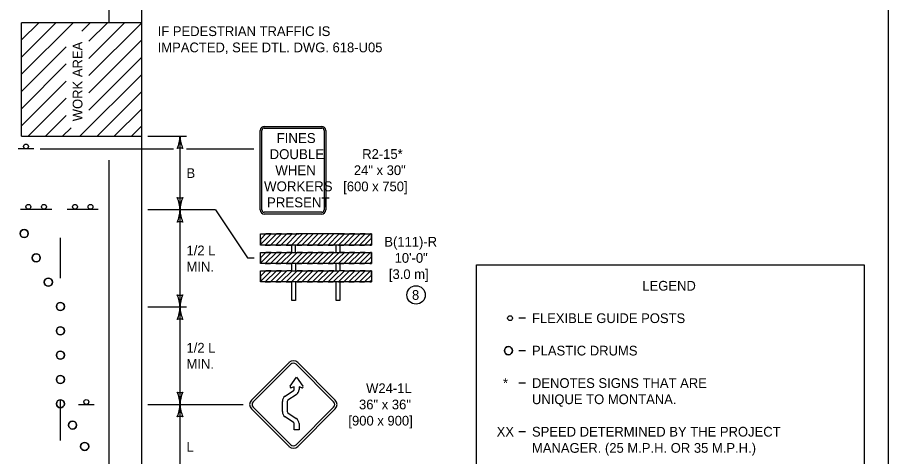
# Model space of a CAD drawing. Extents: x 49991.4 to 50021, y 49987.6 to 50011.4.
# Drawn here: x 50003.24 to 50008.61, y 50003.54 to 50006.25 of the extents above; entities that cross this region are included whole.
import ezdxf

# ---------------------------------------------------------------- set-up
doc = ezdxf.new("R2010")
doc.units = 0
for name, color, linetype in [('Level 1', 7, 'Continuous'), ('Level 2', 7, 'Continuous'), ('Level 3', 7, 'Continuous')]:
    doc.layers.add(name, color=color, linetype=linetype)

msp = doc.modelspace()

# ---------------------------------------------------------------- linework, layer by layer
at = {"layer": 'Level 1'}
for p, q in [((50003.806, 50006.2147), (50003.806, 50011.0404)), ((50004.006, 50011.0404), (50004.006, 50000.2848)), ((50004.006, 50006.2147), (50003.266, 50006.2147)), ((50003.266, 50005.5141), (50003.266, 50006.2147)), ((50003.266, 50006.2147), (50003.266, 50006.2147)), ((50003.266, 50006.1086), (50003.3721, 50006.2147)), ((50003.266, 50006.0025), (50003.4781, 50006.2147)), ((50003.266, 50005.8965), (50003.5842, 50006.2147)), ((50003.6384, 50006.1628), (50003.6903, 50006.2147)), ((50003.6821, 50006.1004), (50003.7963, 50006.2147)), ((50003.6821, 50005.9943), (50003.9024, 50006.2147)), ((50003.6821, 50005.8883), (50004.006, 50006.2122)), ((50003.266, 50005.7904), (50003.5421, 50006.0665)), ((50003.6821, 50005.7822), (50004.006, 50006.1061)), ((50003.266, 50005.6843), (50003.5421, 50005.9604)), ((50003.6821, 50005.6761), (50004.006, 50006.0001)), ((50003.266, 50005.5783), (50003.5421, 50005.8543)), ((50003.6261, 50005.5141), (50004.006, 50005.894)), ((50003.3079, 50005.5141), (50003.5421, 50005.7483)), ((50003.7321, 50005.5141), (50004.006, 50005.7879)), ((50003.8382, 50005.5141), (50004.006, 50005.6819)), ((50003.4139, 50005.5141), (50003.5421, 50005.6422)), ((50003.9443, 50005.5141), (50004.006, 50005.5758)), ((50004.7636, 50005.5749), (50005.118, 50005.5749)), ((50004.9408, 50005.5749), (50004.9408, 50005.5749)), ((50003.52, 50005.5141), (50003.5719, 50005.566)), ((50004.7383, 50005.0601), (50004.7383, 50005.5496)), ((50004.7488, 50005.0601), (50004.7488, 50005.5496)), ((50004.7636, 50005.5643), (50005.118, 50005.5643)), ((50005.1328, 50005.5496), (50005.1328, 50005.0601)), ((50005.1433, 50005.5496), (50005.1433, 50005.0601)), ((50003.266, 50005.5141), (50004.006, 50005.5141)), ((50003.342, 50005.436), (50003.246, 50005.436)), ((50003.806, 50000.2848), (50003.806, 50005.3678)), ((50003.2606, 50005.0638), (50003.3566, 50005.0638)), ((50003.3566, 50005.0638), (50003.4526, 50005.0638)), ((50003.5479, 50005.0638), (50003.6439, 50005.0638)), ((50003.6439, 50005.0638), (50003.7399, 50005.0638)), ((50005.118, 50005.0454), (50004.7636, 50005.0454)), ((50005.118, 50005.0348), (50004.7636, 50005.0348)), ((50003.5061, 50004.6382), (50003.5061, 50004.8882)), ((50004.7404, 50004.8463), (50004.8063, 50004.9121)), ((50004.7404, 50004.8786), (50004.774, 50004.9121)), ((50004.774, 50004.9121), (50004.7404, 50004.8786)), ((50004.7404, 50004.8463), (50004.8063, 50004.9121)), ((50004.7701, 50004.8437), (50004.8385, 50004.9121)), ((50004.8385, 50004.9121), (50004.7701, 50004.8437)), ((50004.8023, 50004.8437), (50004.8707, 50004.9121)), ((50004.8023, 50004.8437), (50004.8707, 50004.9121)), ((50004.8346, 50004.8437), (50004.903, 50004.9121)), ((50004.903, 50004.9121), (50004.8346, 50004.8437)), ((50004.8668, 50004.8437), (50004.9352, 50004.9121)), ((50004.8668, 50004.8437), (50004.9352, 50004.9121)), ((50004.8991, 50004.8437), (50004.9675, 50004.9121)), ((50004.9313, 50004.8437), (50004.9997, 50004.9121)), ((50004.9456, 50004.9121), (50004.977, 50004.9121)), ((50005.205, 50004.9121), (50004.9599, 50004.9121)), ((50004.9638, 50004.8437), (50005.0322, 50004.9121)), ((50004.996, 50004.8437), (50005.0644, 50004.9121)), ((50005.0282, 50004.8437), (50005.0966, 50004.9121)), ((50005.0604, 50004.8437), (50005.1288, 50004.9121)), ((50005.0926, 50004.8437), (50005.161, 50004.9121)), ((50005.1248, 50004.8437), (50005.1932, 50004.9121)), ((50005.157, 50004.8437), (50005.2254, 50004.9121)), ((50005.2254, 50004.9121), (50005.1855, 50004.9121)), ((50005.1892, 50004.8437), (50005.2576, 50004.9121)), ((50005.2215, 50004.8437), (50005.2899, 50004.9121)), ((50005.2899, 50004.9121), (50005.2215, 50004.8437)), ((50005.2537, 50004.8437), (50005.3221, 50004.9121)), ((50005.2537, 50004.8437), (50005.3221, 50004.9121)), ((50005.2859, 50004.8437), (50005.3543, 50004.9121)), ((50005.3543, 50004.9121), (50005.2859, 50004.8437)), ((50005.3182, 50004.8437), (50005.3866, 50004.9121)), ((50005.3182, 50004.8437), (50005.3866, 50004.9121)), ((50005.3505, 50004.8437), (50005.4189, 50004.9121)), ((50005.4189, 50004.9121), (50005.3505, 50004.8437)), ((50005.3827, 50004.8437), (50005.4244, 50004.8855)), ((50005.3827, 50004.8437), (50005.4244, 50004.8855)), ((50004.957, 50004.7982), (50004.957, 50004.8437)), ((50005.2078, 50004.7982), (50005.2078, 50004.8437)), ((50005.4149, 50004.8437), (50005.4244, 50004.8533)), ((50005.4244, 50004.8533), (50005.4149, 50004.8437)), ((50004.7404, 50004.7324), (50004.8063, 50004.7982)), ((50004.7404, 50004.7646), (50004.774, 50004.7982)), ((50004.774, 50004.7982), (50004.7404, 50004.7646)), ((50004.7404, 50004.7324), (50004.8063, 50004.7982)), ((50004.7701, 50004.7298), (50004.8385, 50004.7982)), ((50004.8385, 50004.7982), (50004.7701, 50004.7298)), ((50004.8023, 50004.7298), (50004.8707, 50004.7982)), ((50004.8023, 50004.7298), (50004.8707, 50004.7982)), ((50004.8346, 50004.7298), (50004.903, 50004.7982)), ((50004.903, 50004.7982), (50004.8346, 50004.7298)), ((50004.8668, 50004.7298), (50004.9352, 50004.7982)), ((50004.8668, 50004.7298), (50004.9352, 50004.7982)), ((50004.8991, 50004.7298), (50004.9675, 50004.7982)), ((50004.9313, 50004.7298), (50004.9997, 50004.7982)), ((50004.9635, 50004.7298), (50005.0319, 50004.7982)), ((50004.9958, 50004.7298), (50005.0642, 50004.7982)), ((50005.028, 50004.7298), (50005.0964, 50004.7982)), ((50005.0603, 50004.7298), (50005.1287, 50004.7982)), ((50005.0925, 50004.7298), (50005.1609, 50004.7982)), ((50005.1247, 50004.7298), (50005.1931, 50004.7982)), ((50005.157, 50004.7298), (50005.2192, 50004.792)), ((50005.2192, 50004.7598), (50005.2576, 50004.7982)), ((50005.2192, 50004.792), (50005.2254, 50004.7982)), ((50005.2215, 50004.7298), (50005.2899, 50004.7982)), ((50005.2899, 50004.7982), (50005.2215, 50004.7298)), ((50005.2537, 50004.7298), (50005.3221, 50004.7982)), ((50005.2537, 50004.7298), (50005.3221, 50004.7982)), ((50005.2859, 50004.7298), (50005.3543, 50004.7982)), ((50005.3543, 50004.7982), (50005.2859, 50004.7298)), ((50005.3182, 50004.7298), (50005.3866, 50004.7982)), ((50005.3182, 50004.7298), (50005.3866, 50004.7982)), ((50005.3505, 50004.7298), (50005.4189, 50004.7982)), ((50005.4189, 50004.7982), (50005.3505, 50004.7298)), ((50005.3827, 50004.7298), (50005.4244, 50004.7715)), ((50005.3827, 50004.7298), (50005.4244, 50004.7715)), ((50005.1892, 50004.7298), (50005.2192, 50004.7598)), ((50005.4149, 50004.7298), (50005.4244, 50004.7393)), ((50005.4244, 50004.7393), (50005.4149, 50004.7298)), ((50004.7404, 50004.6184), (50004.8063, 50004.6842)), ((50004.7404, 50004.6506), (50004.774, 50004.6842)), ((50004.774, 50004.6842), (50004.7404, 50004.6506)), ((50004.7404, 50004.6184), (50004.8063, 50004.6842)), ((50004.7701, 50004.6158), (50004.8385, 50004.6842)), ((50004.8385, 50004.6842), (50004.7701, 50004.6158)), ((50004.8023, 50004.6158), (50004.8707, 50004.6842)), ((50004.8023, 50004.6158), (50004.8707, 50004.6842)), ((50004.8346, 50004.6158), (50004.903, 50004.6842)), ((50004.903, 50004.6842), (50004.8346, 50004.6158)), ((50004.8668, 50004.6158), (50004.9352, 50004.6842)), ((50004.8668, 50004.6158), (50004.9352, 50004.6842)), ((50004.8991, 50004.6158), (50004.9675, 50004.6842)), ((50004.9675, 50004.6842), (50004.8991, 50004.6158)), ((50004.9313, 50004.6158), (50004.9997, 50004.6842)), ((50004.9313, 50004.6158), (50004.9997, 50004.6842)), ((50004.9635, 50004.6158), (50005.0319, 50004.6842)), ((50005.0319, 50004.6842), (50004.9635, 50004.6158)), ((50004.9958, 50004.6158), (50005.0642, 50004.6842)), ((50004.9958, 50004.6158), (50005.0642, 50004.6842)), ((50005.028, 50004.6158), (50005.0964, 50004.6842)), ((50005.0964, 50004.6842), (50005.028, 50004.6158)), ((50005.0603, 50004.6158), (50005.1287, 50004.6842)), ((50005.0603, 50004.6158), (50005.1287, 50004.6842)), ((50005.0925, 50004.6158), (50005.1609, 50004.6842)), ((50005.1609, 50004.6842), (50005.0925, 50004.6158)), ((50005.1247, 50004.6158), (50005.1931, 50004.6842)), ((50005.1247, 50004.6158), (50005.1931, 50004.6842)), ((50005.157, 50004.6158), (50005.2254, 50004.6842)), ((50005.2254, 50004.6842), (50005.157, 50004.6158)), ((50005.1892, 50004.6158), (50005.2576, 50004.6842)), ((50005.1892, 50004.6158), (50005.2576, 50004.6842)), ((50005.2215, 50004.6158), (50005.2899, 50004.6842)), ((50005.2899, 50004.6842), (50005.2215, 50004.6158)), ((50005.2537, 50004.6158), (50005.3221, 50004.6842)), ((50005.2537, 50004.6158), (50005.3221, 50004.6842)), ((50005.2859, 50004.6158), (50005.3543, 50004.6842)), ((50005.3543, 50004.6842), (50005.2859, 50004.6158)), ((50005.3182, 50004.6158), (50005.3866, 50004.6842)), ((50005.3182, 50004.6158), (50005.3866, 50004.6842)), ((50005.3505, 50004.6158), (50005.4189, 50004.6842)), ((50005.4189, 50004.6842), (50005.3505, 50004.6158)), ((50005.3827, 50004.6158), (50005.4244, 50004.6576)), ((50005.3827, 50004.6158), (50005.4244, 50004.6576)), ((50005.4149, 50004.6158), (50005.4244, 50004.6254)), ((50005.4244, 50004.6254), (50005.4149, 50004.6158)), ((50004.9237, 50003.9722), (50004.963, 50004.0295)), ((50004.963, 50004.0295), (50005.0024, 50003.9722)), ((50004.9481, 50003.9687), (50004.9304, 50003.9631)), ((50004.9481, 50003.9526), (50004.9481, 50003.9687)), ((50004.9957, 50003.9631), (50004.978, 50003.9687)), ((50004.978, 50003.9687), (50004.978, 50003.9526)), ((50004.8922, 50003.9107), (50004.9443, 50003.9456)), ((50004.961, 50003.9207), (50004.9089, 50003.8858)), ((50003.5061, 50003.6382), (50003.5061, 50003.8882)), ((50003.618, 50003.8606), (50003.714, 50003.8606)), ((50004.8752, 50003.8163), (50004.8752, 50003.8787)), ((50004.9052, 50003.8787), (50004.9051, 50003.8163)), ((50004.9088, 50003.8093), (50004.9612, 50003.7737)), ((50004.9444, 50003.7489), (50004.892, 50003.7845)), ((50004.9481, 50003.7034), (50004.9481, 50003.7415)), ((50004.978, 50003.7034), (50004.9481, 50003.7034)), ((50004.978, 50003.7423), (50004.978, 50003.7034))]:
    msp.add_line(p, q, dxfattribs=at)
msp.add_lwpolyline([(50008.6146, 50011.2628), (50000.3356, 50011.2628), (50000.3356, 50000.0624), (50008.6146, 50000.0624)], close=True, dxfattribs=at)
for points in [[(50005.2192, 50004.8437), (50004.7404, 50004.8437), (50004.7404, 50004.9121), (50004.9456, 50004.9121)], [(50004.7404, 50004.8786), (50004.7404, 50004.8463)], [(50004.8063, 50004.9121), (50004.774, 50004.9121)], [(50004.8707, 50004.9121), (50004.8385, 50004.9121)], [(50004.9997, 50004.9121), (50004.977, 50004.9121), (50004.9675, 50004.9121), (50004.8991, 50004.8437), (50004.9313, 50004.8437), (50004.9997, 50004.9121)], [(50004.9352, 50004.9121), (50004.903, 50004.9121)], [(50005.0644, 50004.9121), (50005.0322, 50004.9121), (50004.9638, 50004.8437), (50004.996, 50004.8437), (50005.0644, 50004.9121)], [(50005.1288, 50004.9121), (50005.0966, 50004.9121), (50005.0282, 50004.8437), (50005.0604, 50004.8437), (50005.1288, 50004.9121)], [(50005.1932, 50004.9121), (50005.1855, 50004.9121), (50005.161, 50004.9121), (50005.0926, 50004.8437), (50005.1248, 50004.8437), (50005.1932, 50004.9121)], [(50005.157, 50004.8437), (50005.1892, 50004.8437), (50005.2576, 50004.9121), (50005.2254, 50004.9121), (50005.157, 50004.8437)], [(50005.2192, 50004.9121), (50005.4244, 50004.9121), (50005.4244, 50004.8437), (50005.2192, 50004.8437)], [(50005.3221, 50004.9121), (50005.2899, 50004.9121)], [(50005.3866, 50004.9121), (50005.3543, 50004.9121)], [(50005.4244, 50004.8855), (50005.4244, 50004.9121), (50005.4189, 50004.9121)], [(50004.7701, 50004.8437), (50004.8023, 50004.8437)], [(50004.8346, 50004.8437), (50004.8668, 50004.8437)], [(50004.9342, 50004.7981), (50004.9342, 50004.8437)], [(50005.2215, 50004.8437), (50005.2537, 50004.8437)], [(50005.2306, 50004.8437), (50005.2306, 50004.7982)], [(50005.2859, 50004.8437), (50005.3182, 50004.8437)], [(50005.3505, 50004.8437), (50005.3827, 50004.8437)], [(50005.4149, 50004.8437), (50005.4244, 50004.8437), (50005.4244, 50004.8533)], [(50005.2192, 50004.7982), (50005.4244, 50004.7982), (50005.4244, 50004.7298), (50004.7404, 50004.7298), (50004.7404, 50004.7982), (50005.2192, 50004.7982)], [(50004.8063, 50004.7982), (50004.774, 50004.7982)], [(50004.8707, 50004.7982), (50004.8385, 50004.7982)], [(50004.9997, 50004.7982), (50004.9675, 50004.7982), (50004.8991, 50004.7298), (50004.9313, 50004.7298), (50004.9997, 50004.7982)], [(50004.9352, 50004.7982), (50004.903, 50004.7982)], [(50005.0642, 50004.7982), (50005.0319, 50004.7982), (50004.9635, 50004.7298), (50004.9958, 50004.7298), (50005.0642, 50004.7982)], [(50005.1287, 50004.7982), (50005.0964, 50004.7982), (50005.028, 50004.7298), (50005.0603, 50004.7298), (50005.1287, 50004.7982)], [(50005.1931, 50004.7982), (50005.1609, 50004.7982), (50005.0925, 50004.7298), (50005.1247, 50004.7298), (50005.1931, 50004.7982)], [(50005.157, 50004.7298), (50005.1892, 50004.7298), (50005.2192, 50004.7598), (50005.2576, 50004.7982), (50005.2306, 50004.7982), (50005.2254, 50004.7982), (50005.2192, 50004.792), (50005.157, 50004.7298)], [(50005.3221, 50004.7982), (50005.2899, 50004.7982)], [(50005.3866, 50004.7982), (50005.3543, 50004.7982)], [(50005.4244, 50004.7715), (50005.4244, 50004.7982), (50005.4189, 50004.7982)], [(50004.7404, 50004.7646), (50004.7404, 50004.7324)], [(50004.7701, 50004.7298), (50004.8023, 50004.7298)], [(50004.8346, 50004.7298), (50004.8668, 50004.7298)], [(50004.9342, 50004.6842), (50004.9342, 50004.7298)], [(50004.957, 50004.7298), (50004.957, 50004.6842)], [(50005.2078, 50004.6842), (50005.2078, 50004.7298)], [(50005.2215, 50004.7298), (50005.2537, 50004.7298)], [(50005.2306, 50004.7298), (50005.2306, 50004.6842)], [(50005.2859, 50004.7298), (50005.3182, 50004.7298)], [(50005.3505, 50004.7298), (50005.3827, 50004.7298)], [(50005.4149, 50004.7298), (50005.4244, 50004.7298), (50005.4244, 50004.7393)], [(50005.2576, 50004.6842), (50005.4244, 50004.6842), (50005.4244, 50004.6158), (50004.7404, 50004.6158), (50004.7404, 50004.6842), (50004.903, 50004.6842)], [(50004.8063, 50004.6842), (50004.774, 50004.6842)], [(50004.8707, 50004.6842), (50004.8385, 50004.6842)], [(50004.9352, 50004.6842), (50004.903, 50004.6842)], [(50004.9352, 50004.6842), (50005.2254, 50004.6842)], [(50004.9997, 50004.6842), (50004.9675, 50004.6842)], [(50005.0642, 50004.6842), (50005.0319, 50004.6842)], [(50005.1287, 50004.6842), (50005.0964, 50004.6842)], [(50005.1931, 50004.6842), (50005.1609, 50004.6842)], [(50005.2576, 50004.6842), (50005.2254, 50004.6842)], [(50005.3221, 50004.6842), (50005.2899, 50004.6842)], [(50005.3866, 50004.6842), (50005.3543, 50004.6842)], [(50005.4244, 50004.6576), (50005.4244, 50004.6842), (50005.4189, 50004.6842)], [(50004.7404, 50004.6506), (50004.7404, 50004.6184)], [(50004.7701, 50004.6158), (50004.8023, 50004.6158)], [(50004.8346, 50004.6158), (50004.8668, 50004.6158)], [(50004.8991, 50004.6158), (50004.9313, 50004.6158)], [(50004.957, 50004.6157), (50004.957, 50004.5017), (50004.9342, 50004.5017), (50004.9342, 50004.6157)], [(50004.9635, 50004.6158), (50004.9958, 50004.6158)], [(50005.028, 50004.6158), (50005.0603, 50004.6158)], [(50005.0925, 50004.6158), (50005.1247, 50004.6158)], [(50005.157, 50004.6158), (50005.1892, 50004.6158)], [(50005.2306, 50004.6157), (50005.2306, 50004.5017), (50005.2078, 50004.5017), (50005.2078, 50004.6157)], [(50005.2215, 50004.6158), (50005.2537, 50004.6158)], [(50005.2859, 50004.6158), (50005.3182, 50004.6158)], [(50005.3505, 50004.6158), (50005.3827, 50004.6158)], [(50005.4149, 50004.6158), (50005.4244, 50004.6158), (50005.4244, 50004.6254)], [(50004.9162, 50004.1187), (50004.6846, 50003.8872)], [(50004.9265, 50004.1083), (50004.695, 50003.8768)], [(50005.1912, 50003.8768), (50004.9596, 50004.1083)], [(50005.2016, 50003.8872), (50004.97, 50004.1187)], [(50004.6846, 50003.8333), (50004.9162, 50003.6018)], [(50004.695, 50003.8437), (50004.9265, 50003.6121)], [(50004.9596, 50003.6121), (50005.1912, 50003.8437)], [(50004.97, 50003.6018), (50005.2016, 50003.8333)]]:
    msp.add_lwpolyline(points, dxfattribs=at)
for centre, radius in [((50003.2939, 50005.4512), 0.0152), ((50003.3086, 50005.079), 0.0152), ((50003.4046, 50005.079), 0.0152), ((50003.5959, 50005.079), 0.0152), ((50003.6919, 50005.079), 0.0152), ((50003.2824, 50004.9144), 0.025), ((50003.357, 50004.7644), 0.025), ((50003.4315, 50004.6144), 0.025), ((50003.5061, 50004.4644), 0.025), ((50006.2799, 50004.3923), 0.015), ((50003.5061, 50004.3144), 0.025), ((50003.5061, 50004.1644), 0.025), ((50006.2699, 50004.1923), 0.025), ((50003.5061, 50004.0144), 0.025), ((50003.5061, 50003.8644), 0.025), ((50003.666, 50003.8758), 0.0152), ((50003.5811, 50003.733), 0.025), ((50003.656, 50003.6015), 0.025)]:
    msp.add_circle(centre, radius, dxfattribs=at)
for centre, radius, start, end in [((50004.7636, 50005.5496), 0.0253, 90, 180), ((50005.118, 50005.5496), 0.0253, 0, 90), ((50004.7636, 50005.5496), 0.0148, 90, 180), ((50005.118, 50005.5496), 0.0148, 0, 90), ((50004.7636, 50005.0601), 0.0253, 180, 270), ((50004.7636, 50005.0601), 0.0148, 180, 270), ((50005.118, 50005.0601), 0.0148, 270, 360), ((50005.118, 50005.0601), 0.0253, 270, 360), ((50003.2824, 50004.9144), 0.025, 0, 180), ((50003.2824, 50004.9144), 0.025, 180, 0), ((50003.357, 50004.7644), 0.025, 0, 180), ((50003.357, 50004.7644), 0.025, 180, 0), ((50003.4315, 50004.6144), 0.025, 0, 180), ((50003.4315, 50004.6144), 0.025, 180, 0), ((50003.5061, 50004.4644), 0.025, 0, 180), ((50003.5061, 50004.4644), 0.025, 180, 0), ((50003.5061, 50004.3144), 0.025, 0, 180), ((50003.5061, 50004.3144), 0.025, 180, 0), ((50003.5061, 50004.1644), 0.025, 0, 180), ((50006.2699, 50004.1923), 0.025, 360, 180), ((50006.2699, 50004.1923), 0.025, 180, 0), ((50003.5061, 50004.1644), 0.025, 180, 0), ((50004.9431, 50004.0918), 0.0381, 45, 135), ((50004.9431, 50004.0918), 0.0234, 45, 135), ((50003.5061, 50004.0144), 0.025, 0, 180), ((50003.5061, 50004.0144), 0.025, 180, 0), ((50004.9286, 50003.9688), 0.00599, 145.4837, 287.3618), ((50004.9975, 50003.9688), 0.00599, 252.6382, 34.5163), ((50004.9136, 50003.8787), 0.0384, 123.8239, 180), ((50004.9396, 50003.9526), 0.0085, 303.8239, 360), ((50004.9396, 50003.9526), 0.0384, 303.8239, 0), ((50003.5061, 50003.8644), 0.025, 0, 180), ((50003.5061, 50003.8644), 0.025, 180, 0), ((50004.7115, 50003.8602), 0.0381, 135, 225), ((50004.7115, 50003.8602), 0.0234, 135, 225), ((50004.9136, 50003.8787), 0.0085, 123.8239, 180), ((50005.1746, 50003.8602), 0.0234, 315, 45), ((50005.1746, 50003.8602), 0.0381, 315, 45), ((50004.9136, 50003.8163), 0.0384, 179.9518, 235.7905), ((50004.9136, 50003.8163), 0.0085, 179.9486, 235.7905), ((50003.5811, 50003.733), 0.025, 0, 180), ((50004.9396, 50003.7419), 0.0085, 357.2362, 55.7905), ((50004.9396, 50003.7419), 0.0384, 0, 55.7905), ((50003.5811, 50003.733), 0.025, 180, 0), ((50003.656, 50003.6015), 0.025, 0, 180), ((50003.656, 50003.6015), 0.025, 180, 0), ((50004.9431, 50003.6287), 0.0381, 225, 315), ((50004.9431, 50003.6287), 0.0234, 225, 315)]:
    msp.add_arc(centre, radius, start, end, dxfattribs=at)
at = {"layer": 'Level 2'}
for p, q in [((50006.0725, 50002.9623), (50006.0725, 50004.7223)), ((50006.0725, 50004.7223), (50008.4639, 50004.7223)), ((50008.4639, 50004.7223), (50008.4639, 50002.9623)), ((50006.3749, 50004.3923), (50006.3349, 50004.3923)), ((50006.3349, 50004.1923), (50006.3749, 50004.1923)), ((50006.3749, 50003.9923), (50006.3349, 50003.9923)), ((50006.3749, 50003.6923), (50006.3349, 50003.6923))]:
    msp.add_line(p, q, dxfattribs=at)
msp.add_circle((50005.6998, 50004.5356), 0.0569, dxfattribs=at)
at = {"layer": 'Level 3'}
for p, q in [((50004.046, 50005.5141), (50004.284, 50005.5141)), ((50004.244, 50005.0602), (50004.244, 50005.5141)), ((50003.382, 50005.436), (50004.204, 50005.436)), ((50004.284, 50005.436), (50004.6255, 50005.436)), ((50004.6232, 50005.436), (50004.6983, 50005.436)), ((50004.4619, 50005.0602), (50004.046, 50005.0602)), ((50004.244, 50004.4602), (50004.244, 50005.0602)), ((50004.4619, 50005.0602), (50004.6605, 50004.7646)), ((50004.6604, 50004.7646), (50004.7004, 50004.7646)), ((50004.284, 50004.4602), (50004.046, 50004.4602)), ((50004.244, 50003.8602), (50004.244, 50004.4602)), ((50004.046, 50003.8602), (50004.6334, 50003.8602)), ((50004.244, 50003.3385), (50004.244, 50003.8602))]:
    msp.add_line(p, q, dxfattribs=at)
for centre, radius, start, end in [((50004.0219, 50005.5233), 0.2223, 337.456, 357.6395), ((50004.4767, 50005.5256), 0.233, 182.8273, 202.0772), ((50004.244, 50005.3859), 0.0548, 72.1388, 107.8612), ((50004.244, 50005.1884), 0.0548, 252.1388, 287.8612), ((50004.0113, 50005.0487), 0.233, 2.8273, 22.0772), ((50004.4661, 50005.0511), 0.2223, 157.456, 177.6395), ((50004.0219, 50005.0694), 0.2223, 337.456, 357.6395), ((50004.4767, 50005.0717), 0.233, 182.8273, 202.0772), ((50004.244, 50004.932), 0.0548, 72.1388, 107.8612), ((50004.244, 50004.5884), 0.0548, 252.1388, 287.8612), ((50004.0113, 50004.4487), 0.233, 2.8273, 22.0772), ((50004.4661, 50004.4511), 0.2223, 157.456, 177.6395), ((50004.0219, 50004.4694), 0.2223, 337.456, 357.6395), ((50004.4767, 50004.4717), 0.233, 182.8273, 202.0772), ((50004.244, 50004.332), 0.0548, 72.1388, 107.8612), ((50004.244, 50003.9884), 0.0548, 252.1388, 287.8612), ((50004.0113, 50003.8487), 0.233, 2.8273, 22.0772), ((50004.4661, 50003.8511), 0.2223, 157.456, 177.6395), ((50004.0219, 50003.8694), 0.2223, 337.456, 357.6395), ((50004.4767, 50003.8717), 0.233, 182.8273, 202.0772), ((50004.244, 50003.732), 0.0548, 72.1388, 107.8612)]:
    msp.add_arc(centre, radius, start, end, dxfattribs=at)

# ---------------------------------------------------------------- texts
at = {"layer": 'Level 1'}
for s, p in [('FINES', (50004.8397, 50005.4726)), ('DOUBLE', (50004.7962, 50005.3734)), ('WHEN', (50004.8317, 50005.2743)), ('WORKERS', (50004.7622, 50005.1751)), ('PRESENT', (50004.7803, 50005.076))]:
    msp.add_text(s, height=0.06118, dxfattribs=at).set_placement(p)
at = {"layer": 'Level 2'}
for s, p in [('IF PEDESTRIAN TRAFFIC IS', (50004.106, 50006.1323)), ('IMPACTED, SEE DTL. DWG. 618-U05', (50004.106, 50006.0323)), ('R2-15*', (50005.3678, 50005.3749)), ('B', (50004.284, 50005.2572)), ('24" x 30"', (50005.3162, 50005.2749)), ('[600 x 750]', (50005.2507, 50005.1749)), ('B(111)-R', (50005.5042, 50004.834)), ('1/2 L ', (50004.284, 50004.7802)), ('10\'-0"', (50005.5677, 50004.734)), ('MIN.', (50004.284, 50004.6802)), ('[3.0 m]', (50005.5324, 50004.634)), ('LEGEND', (50007.0957, 50004.5623)), ('8', (50005.6748, 50004.5056)), ('FLEXIBLE GUIDE POSTS', (50006.4149, 50004.3623)), ('1/2 L ', (50004.284, 50004.1802)), ('PLASTIC DRUMS', (50006.4149, 50004.1623)), ('MIN.', (50004.284, 50004.0802)), ('*', (50006.2363, 50003.9623)), ('DENOTES SIGNS THAT ARE', (50006.4149, 50003.9623)), ('W24-1L', (50005.392, 50003.9302)), ('UNIQUE TO MONTANA.', (50006.4149, 50003.8623)), ('36" x 36"', (50005.3481, 50003.8302)), ('[900 x 900]', (50005.2826, 50003.7302)), ('XX', (50006.1971, 50003.6623)), ('SPEED DETERMINED BY THE PROJECT', (50006.4149, 50003.6623)), ('L', (50004.284, 50003.5694)), ('MANAGER. (25 M.P.H. OR 35 M.P.H.)', (50006.4149, 50003.5623))]:
    msp.add_text(s, height=0.06, dxfattribs=at).set_placement(p)
msp.add_text('WORK AREA', height=0.06, rotation=90, dxfattribs=at).set_placement((50003.6421, 50005.6068))

doc.saveas('drawing.dxf')
